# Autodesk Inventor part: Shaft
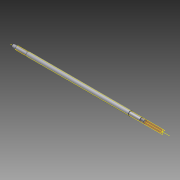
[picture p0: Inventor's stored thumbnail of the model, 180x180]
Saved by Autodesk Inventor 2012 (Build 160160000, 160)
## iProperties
Created: 2007-07
Part Number: Shaft
Material: Steel
Document SubType Name: Modeling
Designer: Ed O'Halloran
Density: 1 g/cm^3
CustomPartVersion: 1
Author: Ed O'Halloran
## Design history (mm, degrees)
sketch "Main Sketch"
  geometry: L1 (0, 0)-(719, 0) reference; L2 (80, 9)-(80, 12); L3 (80, 12)-(640, 12); L4 (700, 10)-(700, 9.899); L5 (640, 10)-(700, 10); L6 (719, 9.899)-(719, 0); L7 (700, 9.899)-(719, 9.899); L8 (640, 12)-(640, 10); L9 (0, 8)-(20, 8); L10 (0, 4)-(0, 8); L11 (20, 8)-(20, 9); L12 (20, 9)-(80, 9); L13 (25, 4)-(25, 0); L14 (0, 4)-(25, 4); L15 (25, 0)-(719, 0)
  constraints: 30 end point, 7 vertical, 4 horizontal
  dimensions: "d3" = 24 diameter of L3 L1 (derived); "d4" = 20 diameter of L5 L1 (derived); "d19" = 19.79899 diameter of L7 L1 (derived); "d29" = 16 diameter of L9 L1 (derived); "d33" = 18 diameter of L12 L1 (derived); "d34" = 8 diameter of L14 L1 (derived)
revolve "Revolution1" sketch "Main Sketch" stored, may be unused: angle "d5" = 0 deg
chamfer "Chamfer8" distance "d35" = 0.5; stored, may be unused: second distance "d36" = 0.125, angle "d37" = 45 deg
feature "iFeature3:1"
chamfer "Chamfer7" distance "d30" = 0.5; stored, may be unused: second distance "d31" = 0.125, angle "d32" = 45 deg
fillet "Fillet2" dims "d23" = 0.5
feature "iFeature1:1"
workaxis "Work Axis1"
workplane "Work Plane1"
workplane "Work Plane2"
chamfer "Chamfer6" distance "d26" = 1.5; stored, may be unused: second distance "d27" = 2, angle "d28" = 45 deg
body "Solid1"
other parameters: "d0" = 0, "d1" = 0, "d2" = 0, "d24" = 90 deg, "d25" = 0
